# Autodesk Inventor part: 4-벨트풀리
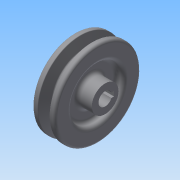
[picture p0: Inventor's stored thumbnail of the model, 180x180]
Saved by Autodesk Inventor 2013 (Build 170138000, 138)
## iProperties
Created: 2011-02
Part Number: 4-벨트풀리
Material: 일반
Document SubType Name: Modeling
Designer: Administrator
Density: 1 g/cm^3
Author: Administrator
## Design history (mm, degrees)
sketch "스케치1"
  geometry: L1 (0, 0)-(-25, 0); L2 (-25, 0)-(-25, 11); L3 (-25, 11)-(-19, 11); L4 (-19, 11)-(-19, 21.5); L5 (-19, 21.5)-(-25, 21.5); L6 (-25, 21.5)-(-25, 35.2); L7 (-25, 35.2)-(-20.325, 35.2); L8 (-20.325, 35.2)-(-17.574, 26.2); L9 (-17.574, 26.2)-(-13.426, 26.2); L10 (-13.426, 26.2)-(-10.675, 35.2); L11 (-10.675, 35.2)-(-6, 35.2); L12 (-6, 35.2)-(-6, 21.5); L13 (-6, 21.5)-(-12, 21.5); L14 (-12, 21.5)-(-12, 11); L15 (-12, 11)-(0, 11); L16 (0, 11)-(0, 0); 2 further points
  constraints: 32 end point, 7 perpendicular, 5 parallel, 4 collinear, 4 equal length, 2 point on line, 1 horizontal, 1 horizontal alignment
  dimensions: "d0" = 25 distance of L1.start L1.end; "d1" = 22 diameter of L15 L1; "d2" = 43 diameter of L5 L1; "d3" = 8 distance of point (-11.5, 32.5) point (-19.5, 32.5); "d4" = 34 deg angle of L10 L8; "d5" = 19 distance of L11.end L6.end; "d6" = 6 distance of L12.end L13.end; "d7" = 65 diameter of point (-19.5, 32.5) L1; "d8" = 2.7 distance from line of point (-19.5, 32.5) L7; "d9" = 6.3 distance from line of L9 point (-19.5, 32.5)
revolve "회전1" sketch "스케치1" stored, may be unused: angle "d10" = 90 deg
sketch "스케치2"
  geometry: L1 (-2, 5.123)-(-2, 7.3); L2 (-2, 7.3)-(2, 7.3); L3 (2, 7.3)-(2, 5.123); C1 r 11 at (0, 0) reference; A1 r 5.5 centre (0, 0) between (-2, 5.123) and (2, 5.123)
  constraints: 6 end point, 2 parallel, 2 point on circle, 1 centre point, 1 coincident, 1 perpendicular, 1 vertical
  dimensions: "d11" = 12.8 dimension on A1 L2; "d13" = 11 diameter of A1; "d14" = 4 distance of L1.end L2.end
extrude "돌출1" cut sketch "스케치2" stored distance "d15" = 10; taper "d16" = 0 deg
fillet "모깎기1" dims "d17" = 1, "d18" = 0.5, "d19" = 2
fillet "모깎기2" dims "d20" = 3
node "솔리드1"
